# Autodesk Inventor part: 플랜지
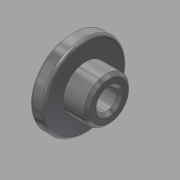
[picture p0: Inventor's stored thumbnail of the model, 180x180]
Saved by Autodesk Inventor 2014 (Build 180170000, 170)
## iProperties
Created: 2018-01
Part Number: 플랜지
Material: 스테인리스강
Document SubType Name: Modeling
Designer: mduedu
Density: 8.08 g/cm^3
Appearance: 반광택
Mass: 3.95967 g
Surface Area: 5.35087 cm^2
Volume: 0.490059 cm^3
Author: mduedu
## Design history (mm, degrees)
sketch "스케치1"
  geometry: L1 (0, 0)-(0, 7); L2 (0, 7)-(2.5, 7); L3 (2.5, 7)-(2.5, 3.75); L4 (2.5, 3.75)-(6.5, 3.75); L5 (6.5, 3.75)-(6.5, 0); L6 (6.5, 0)-(0, 0)
  constraints: 12 end point, 4 parallel, 1 perpendicular, 1 vertical
  dimensions: "d0" = 14 diameter of L2 L6; "d2" = 7.5 diameter of L4 L6; "d3" = 2.5 distance of L1.end L2.end; "d4" = 6.5 distance between parallel lines of L5 L1
revolve "회전1" sketch "스케치1" stored, may be unused: angle "d5" = 90 deg
hole "구멍1" diameter "d8" = 3.5; stored, may be unused: countersink angle "d12" = 90 deg, drill point angle "d14" = 118 deg; dims "d9" = 6, "d10" = 4, "d11" = 2, "d13" = 8, "d19" = 10, "d20" = 10
fillet "모깎기1" dims "d15" = 0.5
chamfer "모따기1" distance "d16" = 0.5; stored, may be unused: second distance "d17" = 2, angle "d18" = 45 deg
chamfer "모따기2" distance "d21" = 0.5; stored, may be unused: second distance "d22" = 2, angle "d23" = 45 deg
node "솔리드1"
